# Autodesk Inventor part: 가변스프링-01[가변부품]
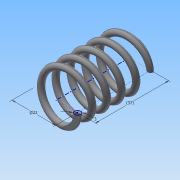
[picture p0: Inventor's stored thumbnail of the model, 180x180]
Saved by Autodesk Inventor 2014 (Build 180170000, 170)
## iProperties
Created: 2015-09
Part Number: 가변스프링-01[가변부품]
Material: 강철, 탄소
Document SubType Name: Modeling
Designer: study
Density: 7.87 g/cm^3
Appearance: 반연마
Mass: 18.7976 g
Surface Area: 32.4648 cm^2
Volume: 2.38851 cm^3
Author: study
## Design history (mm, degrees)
sketch "스케치1"
  geometry: L1 (0, 0)-(11, 0); L2 (11, 0)-(11, 25.358); L3 (11, 25.358)-(0, 25.358); L4 (0, 25.358)-(0, 0); C1 r 1.5 at (11, 0)
  constraints: 8 end point, 2 parallel, 1 centre point, 1 coincident, 1 horizontal, 1 perpendicular
  dimensions: "d0" = 22 diameter of L2 L4; "d1" = 25.35829 distance of L1.end L2.end (derived); "d2" = 3 diameter of C1
feature "코일1" sketch "스케치1" pitch "d3" = 10; turns "d5" = 5; dims "d4" = 25.35829 (= d1), "d6" = 0, angle "d7" = 90 deg, angle "d8" = 90 deg, "d9" = 0, "d10" = 0
sketch "스케치2"
  geometry: L1 (-12.5, 0)-(-9.5, 0) reference; L2 (-12.5, 0)-(-9.5, 0) reference; 1 further point
  constraints: 2 horizontal alignment
extrude "돌출1" cut sketch "스케치2" stored distance "d11" = 10; taper "d12" = 0 deg
node "작업 평면1"
sketch "스케치3"
  geometry: L1 (-9.5, 0)-(-12.5, 0) reference; 1 further point
  constraints: 1 horizontal alignment
extrude "돌출2" cut sketch "스케치3" stored distance "d14" = 10; taper "d15" = 0 deg
node "솔리드1"
node "절단 모서리 투영1"
node "절단 모서리 투영2"
node "절단 모서리 투영3"
other parameters: "d13" = 25.35829 (= d1)
